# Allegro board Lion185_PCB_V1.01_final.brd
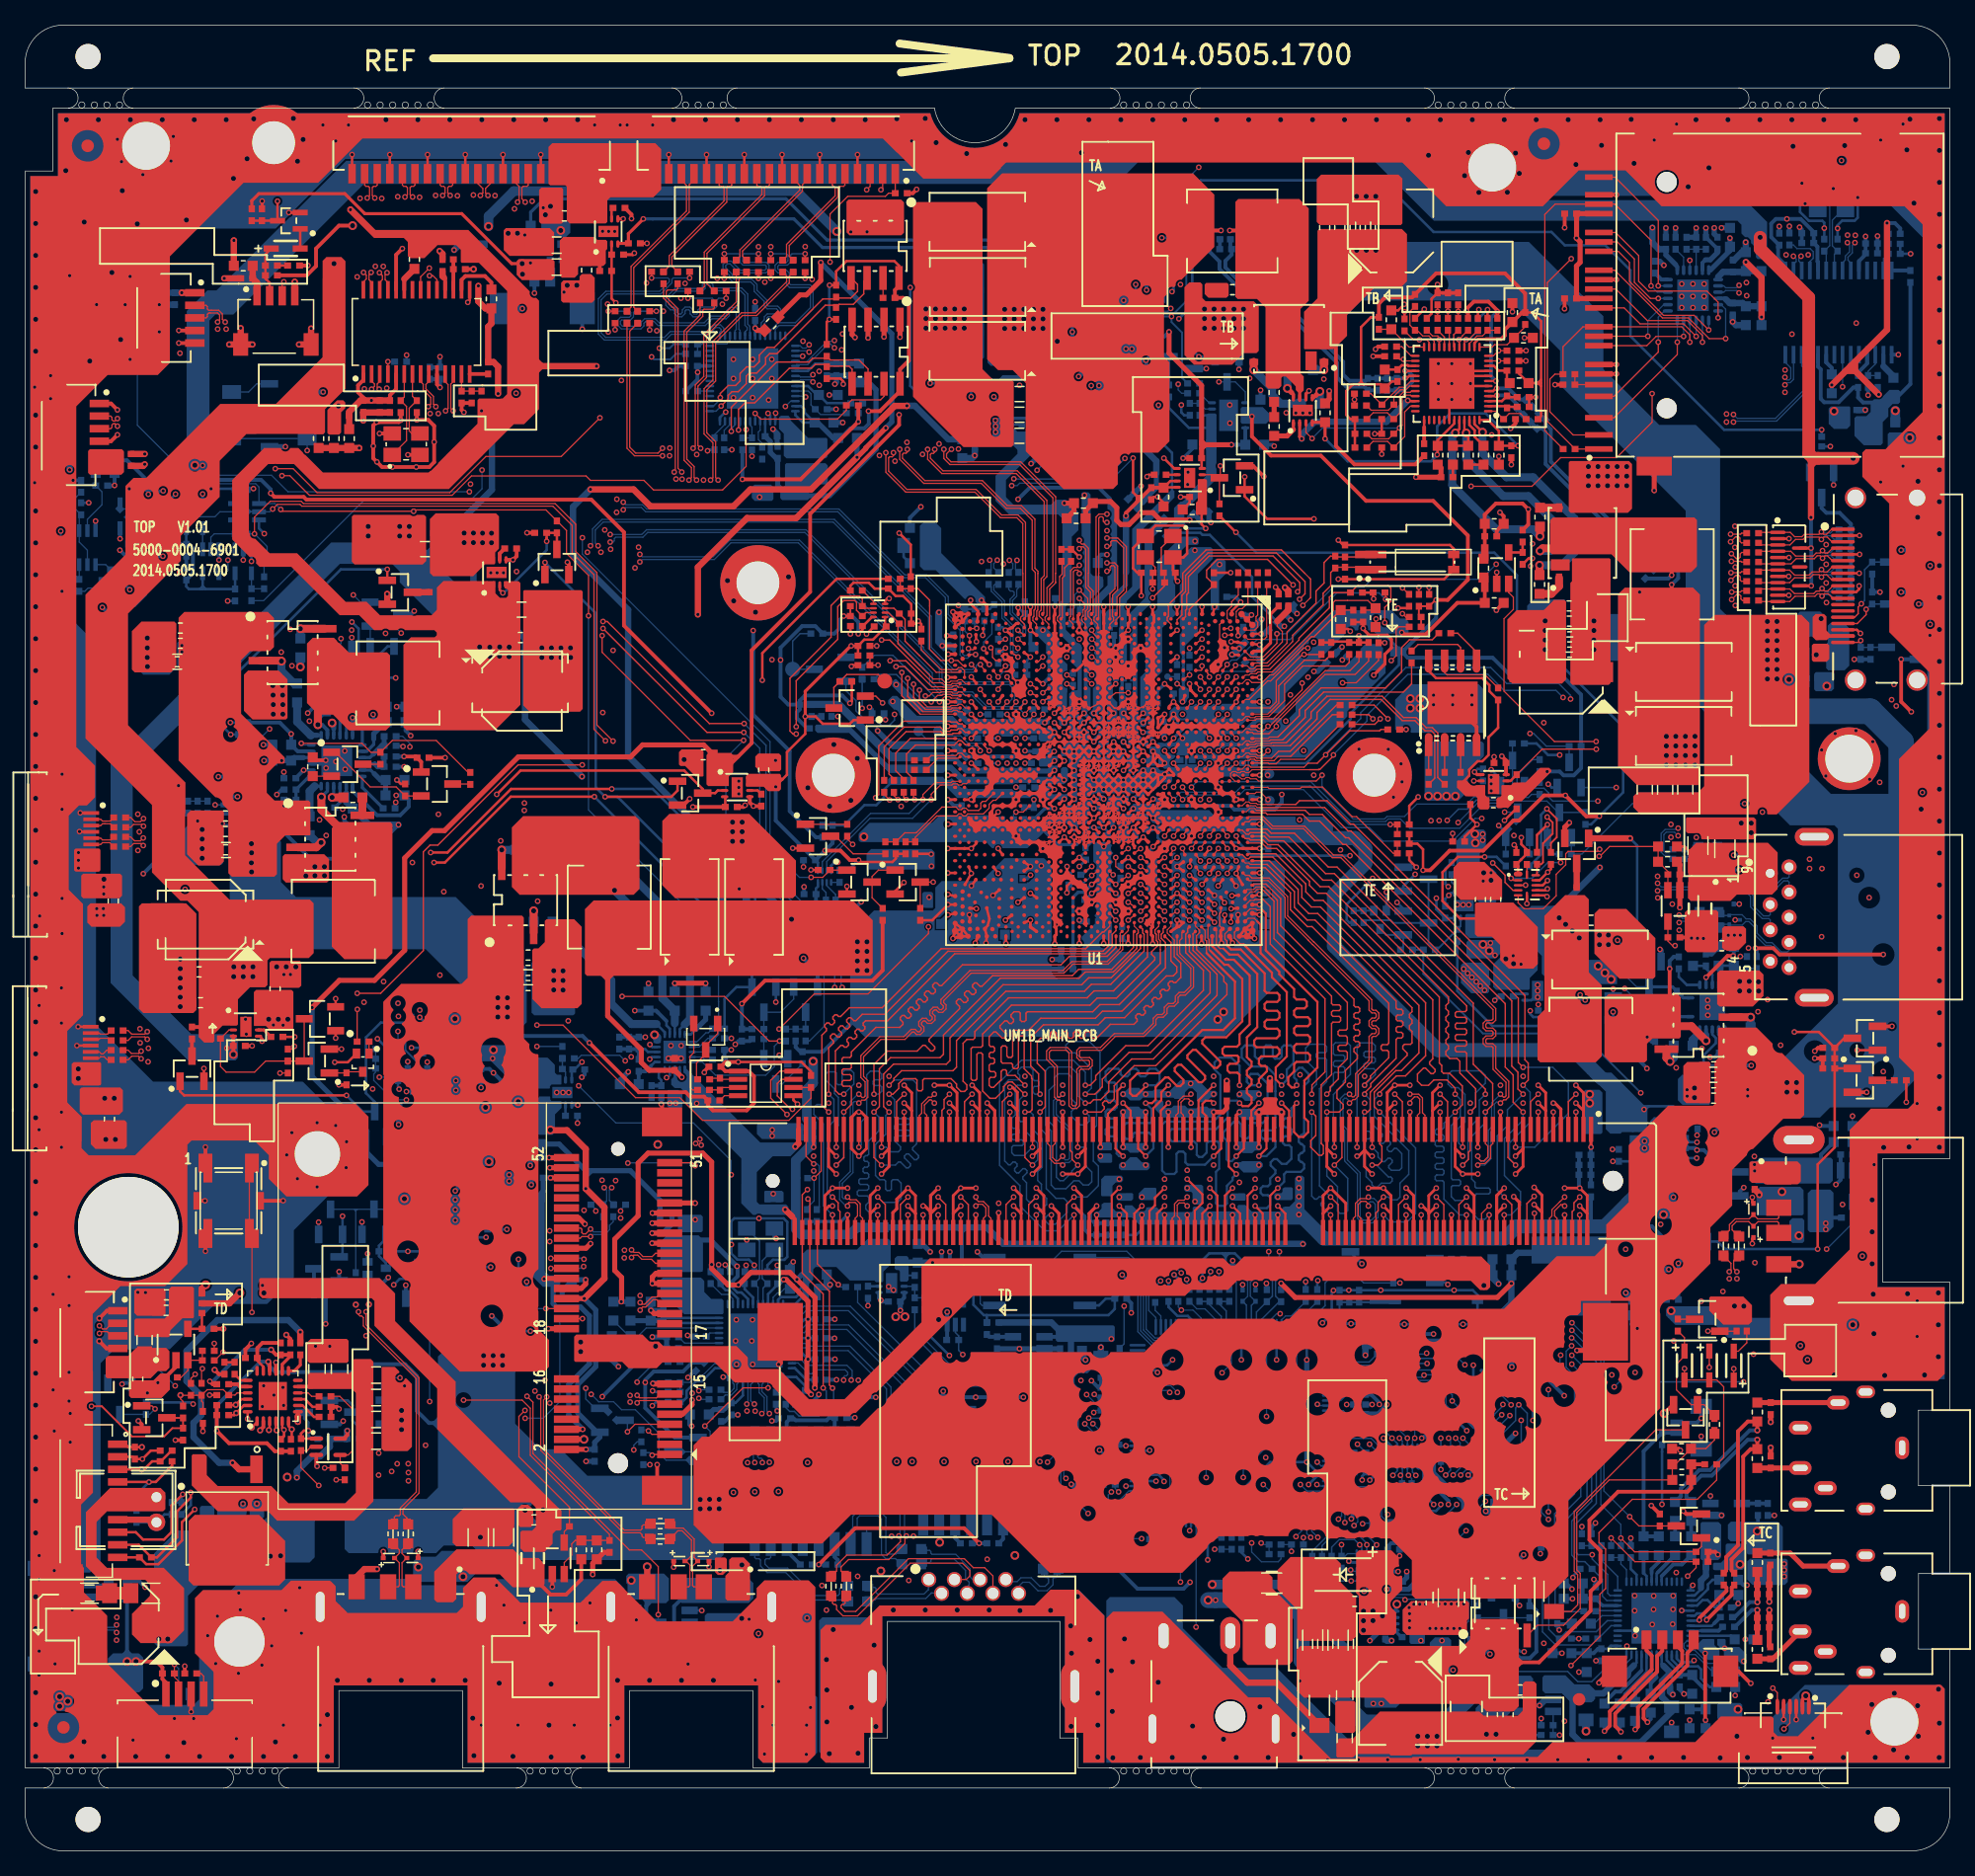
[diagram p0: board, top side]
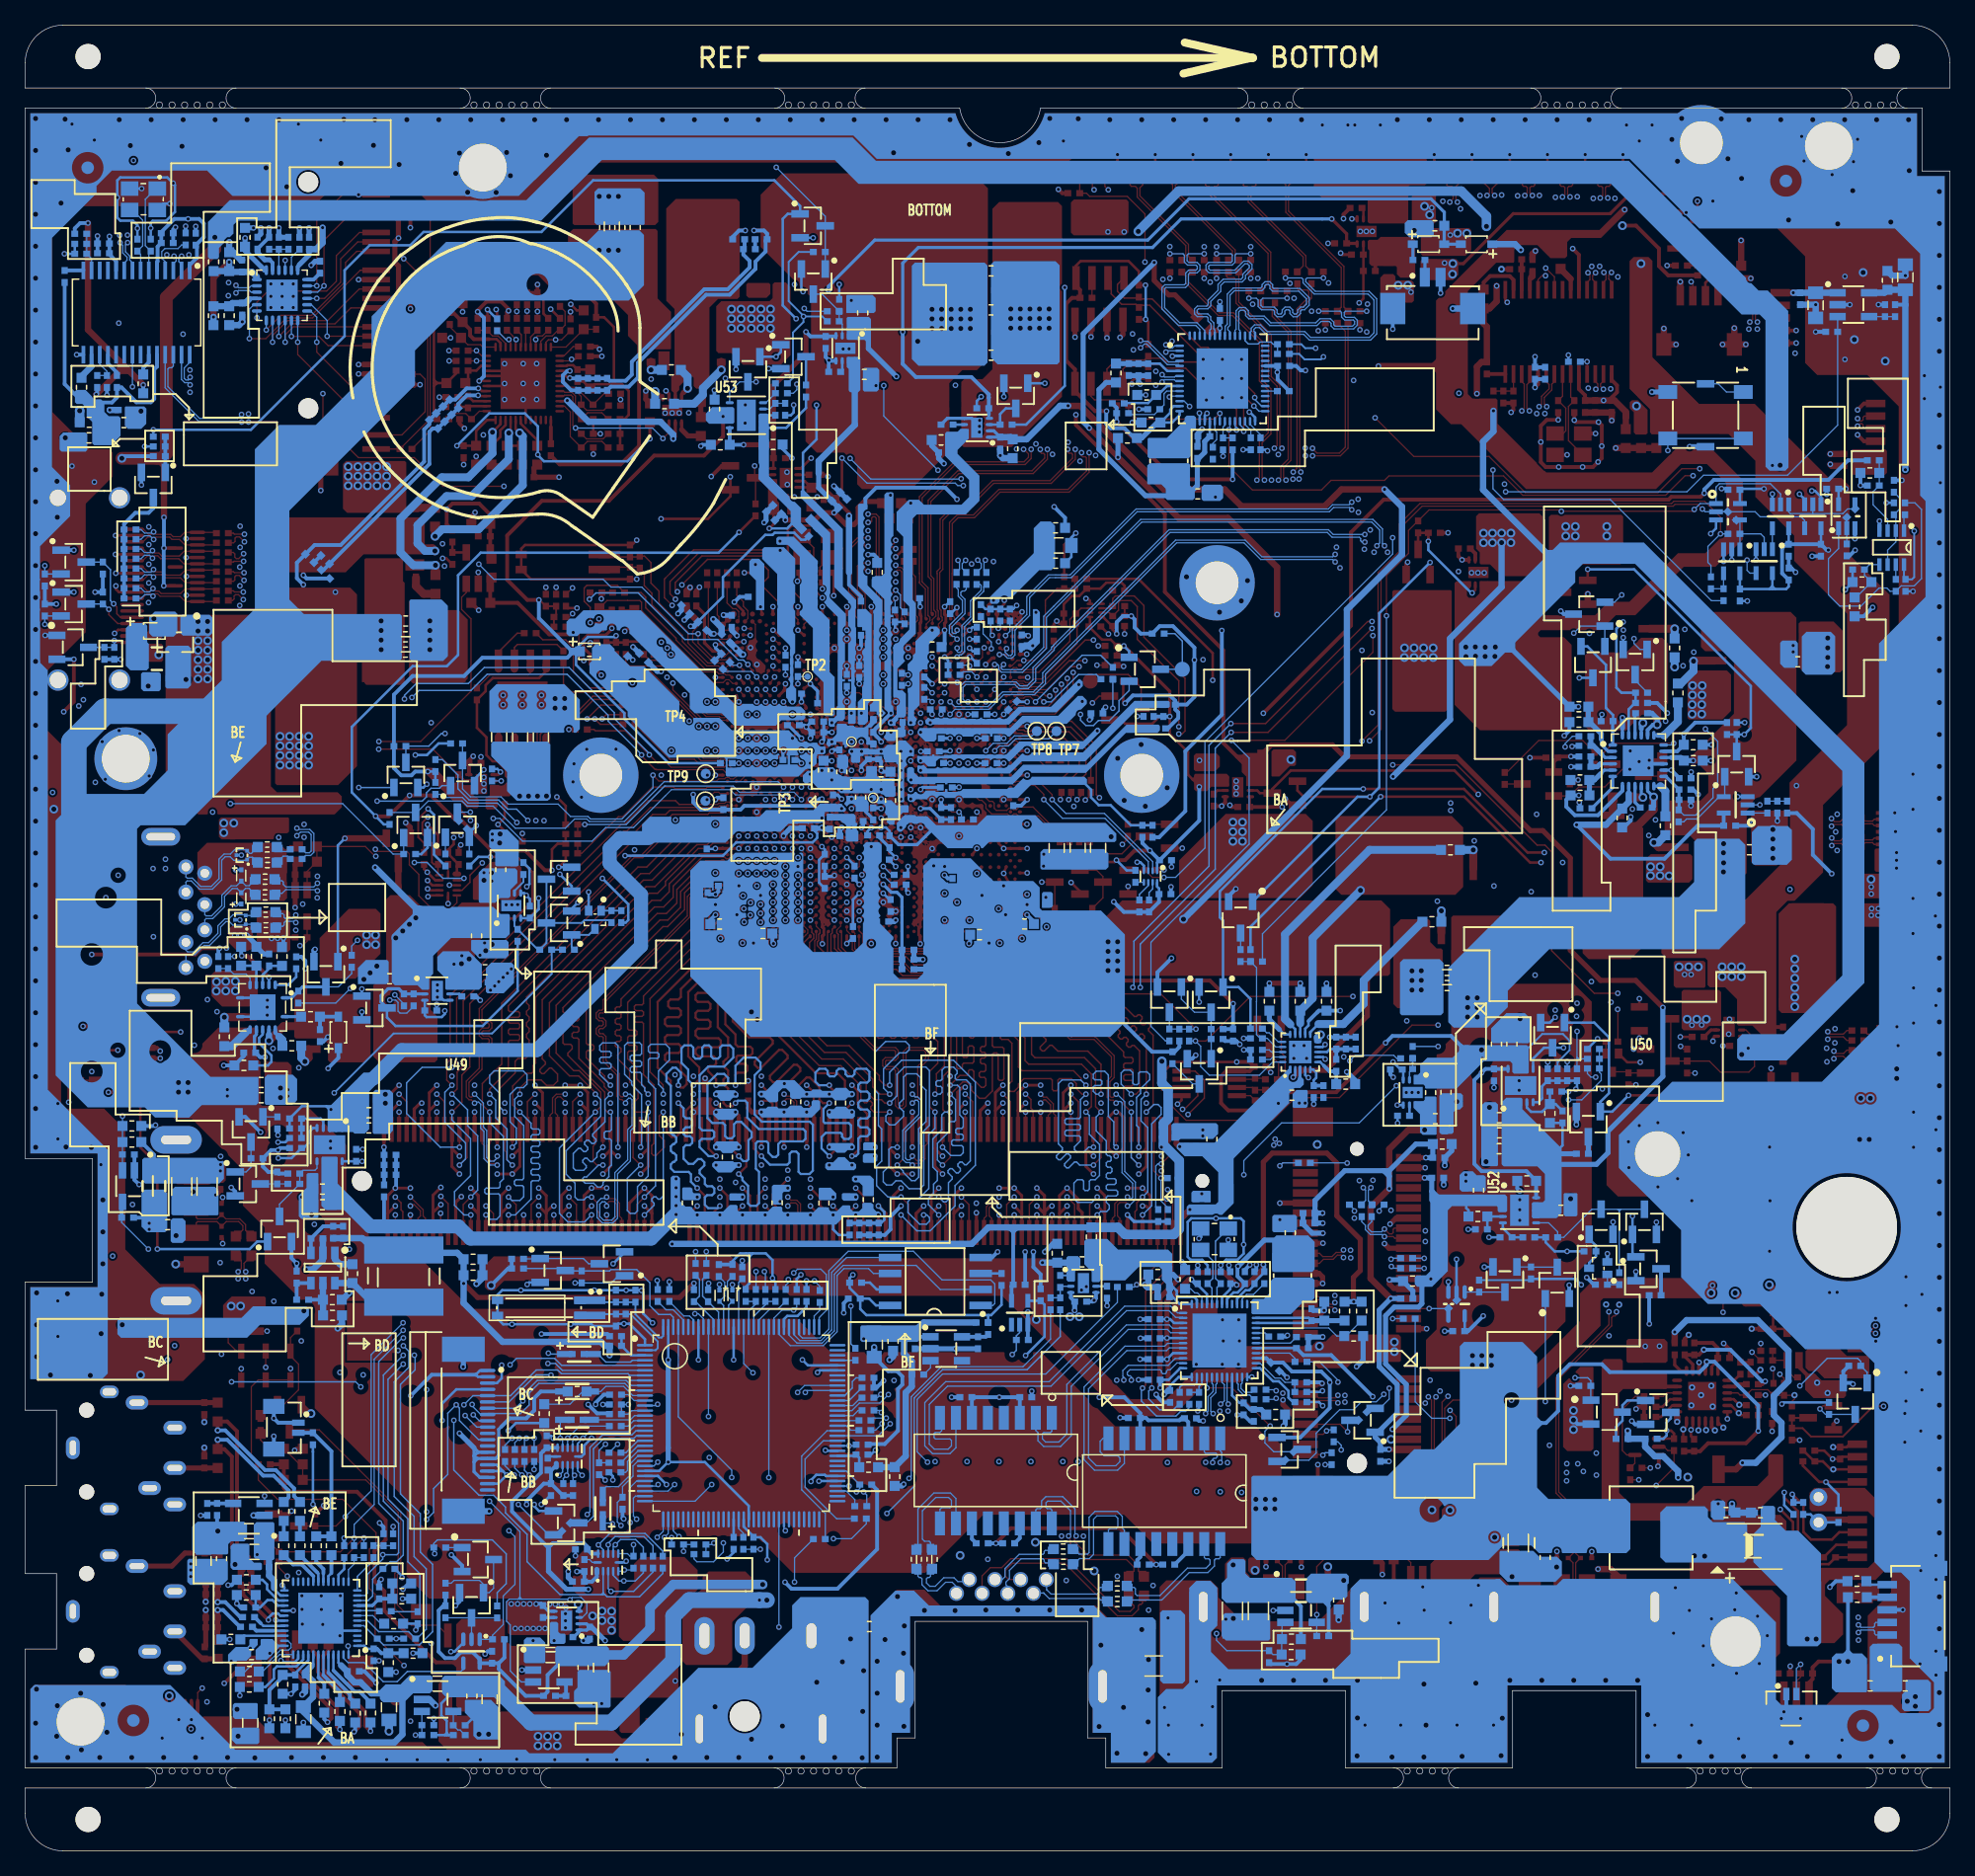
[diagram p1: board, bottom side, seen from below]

Outline 153 x 145.2 mm; copper layers: TOP, LAY2, LAY3, LAY4, LAY5, BOTTOM. Coordinates in mm from the lower left corner of the outline.

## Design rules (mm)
net group 8625_RST#: nets 8625_RST# VDDIO_8625
net group +V3.3A_RTC: nets +V3.3A_RTC VBAT
net group +V5S_HDMI: nets +V5S_HDMI SCL_CONN
net group +V_LED: nets +V_LED N373550150
net group EDP_TXN2: nets EDP_TXN2 EDP_TXN2_CONN
net group EDP_TXN3: nets EDP_TXN3 EDP_TXN3_CONN
net group HDA_BITCLK: nets HDA_BITCLK N370398495
net group HDA_RST#: nets HDA_RST# N370397174
net group HDA_SDATAIN0: nets HDA_SDATAIN0 N371025596
net group HDA_SDATAOUT: nets HDA_SDATAOUT N370398555
net group HDA_SYNC: nets HDA_SYNC N370398430
net group HSON: nets HSON PCIE_RXN0_LAN
net group HSOP: nets HSOP PCIE_RXP0_LAN
net group HUB2_USB_PN1: nets HUB2_USB_PN1 N373557631
net group HUB2_USB_PP1: nets HUB2_USB_PP1 N373557637
net group HUB_USB_PN2: nets HUB_USB_PN2 N373557825
net group HUB_USB_PP2: nets HUB_USB_PP2 N373557823
net group LAN_TX0N: nets LAN_TX0N N373748211
net group LAN_TX0P: nets LAN_TX0P N373748197
net group LAN_TX1N: nets LAN_TX1N N373748171
net group LAN_TX1P: nets LAN_TX1P N373748290
net group LAN_TX2N: nets LAN_TX2N N373748155
net group LAN_TX2P: nets LAN_TX2P N373748367
net group LAN_TX3N: nets LAN_TX3N N373748377
net group LAN_TX3P: nets LAN_TX3P N373748142
net group LAN_VDDEN_SOC: nets LAN_VDDEN_SOC N371123996
net group M_DDR_A_CTRL_IG: nets M_ODT0 M_ODT1
net group M_HDMI_CTL: nets HDMI_CTRLCLK HDMI_CTRLDATA
net group M_HUB2_USB_P2: nets HUB2_USB_PN2 HUB2_USB_PP2
net group M_HUB2_USB_P3: nets HUB2_USB_PN3 HUB2_USB_PP3
net group M_HUB_USB_P3: nets HUB_USB_PN3 HUB_USB_PP3
net group M_HUB_USB_P4: nets HUB_USB_PN4 HUB_USB_PP4
net group M_MDI0: nets MDI0+ MDI0-
net group M_MDI1: nets MDI1+ MDI1-
net group M_MDI2: nets MDI2+ MDI2-
net group M_MDI3: nets MDI3+ MDI3-
net group M_PCIE_RX1_WLAN: nets PCIE_RXN1_WLAN PCIE_RXP1_WLAN
net group M_USB_NFC: nets USB_NFCN USB_NFCP
net group M_USB_P2: nets USB_PN2 USB_PP2
net group M_USB_P3: nets USB_PN3 USB_PP3
net group OUT_CLK+: nets OUT_CLK+ TMDS_CLKP
net group OUT_CLK-: nets OUT_CLK- TMDS_CLKN
net group OUT_D0+: nets OUT_D0+ TMDS_DATAP0
net group OUT_D0-: nets OUT_D0- TMDS_DATAN0
net group OUT_D1+: nets OUT_D1+ TMDS_DATAP1
net group OUT_D1-: nets OUT_D1- TMDS_DATAN1
net group OUT_D2+: nets OUT_D2+ TMDS_DATAP2
net group OUT_D2-: nets OUT_D2- TMDS_DATAN2
net group PCIE_TXN0_LAN: nets N370399343 PCIE_TXN0_LAN
net group PCIE_TXN1_WLAN: nets N370399448 PCIE_TXN1_WLAN
net group PCIE_TXP0_LAN: nets N370399144 PCIE_TXP0_LAN
net group PCIE_TXP1_WLAN: nets N370399202 PCIE_TXP1_WLAN
net group SATA_RXN0: nets N373530908 SATA_RXN0
net group SATA_RXN1: nets N373530772 SATA_RXN1
net group SATA_RXP0: nets N373530977 SATA_RXP0
net group SATA_RXP1: nets N373530802 SATA_RXP1
net group SATA_TXN0: nets N373530916 SATA_TXN0
net group SATA_TXN1: nets N373530783 SATA_TXN1
net group SATA_TXP0: nets N373530914 SATA_TXP0
net group SATA_TXP1: nets N373530781 SATA_TXP1
net group SPI_CLK: nets N371989349 SPI_CLK
net group SPI_CS0#: nets N371989315 SPI_CS0#
net group SPI_SI: nets N371989334 SPI_SI
net group SPI_SO: nets N371989320 SPI_SO
net group USB3_RX0_N: nets N342323571 USB3_RX0_N
net group USB3_RX0_P: nets N342323527 USB3_RX0_P
net group USB_PN0: nets N342323565 USB_PN0
net group USB_PP0: nets N342323609 USB_PP0
net group 40OHM(A_CTL): nets M_CKE0 M_CKE1 M_CS#0 M_CS#1
net group 50OHM: nets H_PROCHOT# SMB_CLK_S2 SMB_DATA_S2
net group 50OHM(A_D0): nets M_A_DQ0 M_A_DQ1 M_A_DQ2 M_A_DQ3 M_A_DQ4 M_A_DQ5 M_A_DQ6 M_A_DQ7
net group 50OHM(A_D1): nets M_A_DQ8 M_A_DQ9 M_A_DQ10 M_A_DQ11 M_A_DQ12 M_A_DQ13 M_A_DQ14 M_A_DQ15
net group 50OHM(A_D2): nets M_A_DQ16 M_A_DQ17 M_A_DQ18 M_A_DQ19 M_A_DQ20 M_A_DQ21 M_A_DQ22 M_A_DQ23
net group 50OHM(A_D3): nets M_A_DQ24 M_A_DQ25 M_A_DQ26 M_A_DQ27 M_A_DQ28 M_A_DQ29 M_A_DQ30 M_A_DQ31
net group 50OHM(A_D4): nets M_A_DQ32 M_A_DQ33 M_A_DQ34 M_A_DQ35 M_A_DQ36 M_A_DQ37 M_A_DQ38 M_A_DQ39
net group 50OHM(A_D5): nets M_A_DQ40 M_A_DQ41 M_A_DQ42 M_A_DQ43 M_A_DQ44 M_A_DQ45 M_A_DQ46 M_A_DQ47
net group 50OHM(A_D6): nets M_A_DQ48 M_A_DQ49 M_A_DQ50 M_A_DQ51 M_A_DQ52 M_A_DQ53 M_A_DQ54 M_A_DQ55
net group 50OHM(A_D7): nets M_A_DQ56 M_A_DQ57 M_A_DQ58 M_A_DQ59 M_A_DQ60 M_A_DQ61 M_A_DQ62 M_A_DQ63
net group 85OHM: nets CLK_PCIE_LAN_N CLK_PCIE_LAN_P CLK_PCIE_WLAN_N CLK_PCIE_WLAN_P
net group AUXN_LVDS: nets AUXN_LVDS EDP_AUXN EDP_AUXN_CONN
net group AUXP_LVDS: nets AUXP_LVDS EDP_AUXP EDP_AUXP_CONN
net group DEFAULT: nets DDR3_DRAM_PWROK DDR3_VCCA_PWROK DDR3L_DRAMRST# EDP_VDDEN
net group EDP_TXN0: nets EDP_TXN0 EDP_TXN0_CONN TXN0_LVDS
net group EDP_TXN1: nets EDP_TXN1 EDP_TXN1_CONN TXN1_LVDS
net group EDP_TXP0: nets EDP_TXP0 EDP_TXP0_CONN TXP0_LVDS
net group EDP_TXP1: nets EDP_TXP1 EDP_TXP1_CONN TXP1_LVDS
net group EDP_TXP2: nets EDP_TXP2 EDP_TXP2_CONN LAO_DATAP2
net group EDP_TXP3: nets EDP_TXP3 EDP_TXP3_CONN LAO_DATAP3
net group GND: nets GND
net group HDMI_CTL_CON: nets SDA_CONN
net group HUB_USB_PN1: nets N373557456
net group HUB_USB_PP1: nets N373557462
net group LPC_CLK_EC: nets LPC_CLK_EC N370732942 N370732965
net group M_DDR_A_CLK: nets M_CLK_DDR0 M_CLK_DDR1 M_CLK_DDR#0 M_CLK_DDR#1
net group M_DDR_A_CMD_IG: nets M_A_A0 M_A_A1 M_A_A2 M_A_A3 M_A_A4 M_A_A5 M_A_A6 M_A_A7 M_A_A8 M_A_A9 M_A_A10 M_A_A11 M_A_A12 M_A_A13 M_A_A14 M_A_A15 M_A_BS0 M_A_BS1 M_A_BS2 M_A_CAS# M_A_RAS# M_A_WE#
net group M_DDR_A_D0: nets M_A_DM0 M_A_DQS0 M_A_DQS#0
net group M_DDR_A_D1: nets M_A_DM1 M_A_DQS1 M_A_DQS#1
net group M_DDR_A_D2: nets M_A_DM2 M_A_DQS2 M_A_DQS#2
net group M_DDR_A_D3: nets M_A_DM3 M_A_DQS3 M_A_DQS#3
net group M_DDR_A_D4: nets M_A_DM4 M_A_DQS4 M_A_DQS#4
net group M_DDR_A_D5: nets M_A_DM5 M_A_DQS5 M_A_DQS#5
net group M_DDR_A_D6: nets M_A_DM6 M_A_DQS6 M_A_DQS#6
net group M_DDR_A_D7: nets M_A_DM7 M_A_DQS7 M_A_DQS#7
net group NET_+V1.05S: nets +V1.05S
net group NET_+V1.8S: nets +V1.8S
net group NET_+V3.3A: nets +V3.3A
net group NET_+V3.3A_KBC: nets +V3.3A_KBC
net group NET_+V3.3S: nets +V3.3S
net group NET_+V5S: nets +V5S
net group NET_AGND: nets AGND
net group NET_BUF_PLT_RST#: nets BUF_PLT_RST#
net group NET_H_RCIN#: nets H_RCIN#
net group NET_KBC_FAN_SPEED: nets KBC_FAN_SPEED
net group NET_PM_SLP_S3#: nets PM_SLP_S3#
net group NET_PM_SLP_S4#: nets PM_SLP_S4#
net group SVID_CLK: nets N370879306 N371989087 SVID_CLK
net group SVID_DATA: nets N370879346 N371989085 SVID_DATA
net group USB3_TX0_N: nets N342323491 N342323907 USB3_TX0_N
net group USB3_TX0_P: nets N342323548 N342323607 USB3_TX0_P
net group USB_BTN: nets USB_BTN
net group USB_BTP: nets USB_BTP
nets with their own width: min track width 0.102; nets CLK_WLAN_OE#

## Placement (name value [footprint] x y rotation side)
C1  100NF  [CC0402N]  82.83 71.66 180 bottom
C3  100NF  [CC0402N]  78.19 101.2 270 bottom
C4  100NF  [CC0402N]  76.59 101.2 270 bottom
C5  100NF  [CC0402N]  77.36 101.2 270 bottom
C6  100NF  [CC0402N]  78.96 101.2 270 bottom
C7  20PF  [CC0402N]  89.2 101.65 0 top
C8  20PF  [CC0402N]  90.96 101.65 180 top
C9  1uF  [CC0603N]  40.94 129.25 180 bottom
C10  1uF  [CC0603N]  107.35 98.08 270 top
C11  12pF  [CC0402N]  104.92 101.62 90 top
C12  1uF  [CC0603N]  104.58 97.93 90 top
C13  100NF  [CC0402N]  100.41 99.48 270 top
C14  12pF  [CC0402N]  104.92 103.38 270 top
C16  100NF  [CC0402N]  114.88 83.7 90 top
C17  1uF  [CC0402N]  118.56 83.34 90 top
C18  1000pF  [CC0402N]  115.89 85.57 270 bottom
C19  100NF  [CC0402N]  117.24 86.52 0 top
C20  0.1u  [CC0402N]  118.54 78.93 90 top
C21  0.1u  [CC0402N]  120.18 78.94 90 top
C22  2.2uF  [CC0603N]  97.79 73.71 180 bottom
C23  2.2uF  [CC0603N]  94.35 72.95 0 bottom
C24  2.2uF  [CC0603N]  77.13 72.87 180 bottom
C25  2.2uF  [CC0603N]  73.56 73.72 0 bottom
C26  0.1u  [CC0402N]  98.75 75.74 270 bottom
C27  0.1u  [CC0402N]  79.28 77.81 90 bottom
C28  0.1u  [CC0402N]  97.42 76.75 180 bottom
C29  0.1u  [CC0402N]  72.34 75.26 0 bottom
C30  1uF  [CC0402N]  84.79 78.83 0 bottom
C31  0.1u  [CC0402N]  84.84 73.91 0 bottom
C32  1uF  [CC0402N]  83.24 88.44 270 bottom
C33  1uF  [CC0402N]  76.4 120.76 0 bottom
C34  1uF  [CC0402N]  76.4 124.11 0 bottom
C35  10uF  [CC0603N]  76.22 125.66 0 bottom
C36  10uF  [CC0603N]  76.22 122.55 0 bottom
C37  10uF  [CC0603N]  76.22 118.95 0 bottom
C38  10uF  [CC0603N]  89.53 85.95 270 bottom
C39  4.7uF  [CC0603N]  84.97 85.82 180 bottom
C40  4.7uF  [CC0603N]  88.08 85.81 90 bottom
C41  2.2uF  [CC0603N]  86.58 83.8 90 bottom
C42  2.2uF  [CC0603N]  84.21 83.53 90 bottom
C43  0.1u  [CC0402N]  86.45 86.83 0 bottom
C44  0.1u  [CC0402N]  84.68 86.82 180 bottom
C45  0.1u  [CC0402N]  84.18 88.11 270 bottom
C46  22uF  [CC0805N]  115.32 88.57 270 bottom
C47  22uF  [CC0805N]  113.65 88.57 270 bottom
C48  22uF  [CC0805N]  112 88.57 270 bottom
C49  1uF  [CC0402N]  97.5 83.29 270 bottom
C50  1uF  [CC0402N]  85.59 82.47 90 bottom
C51  1uF  [CC0402N]  89.43 77.02 90 bottom
C52  1uF  [CC0402N]  89.43 78.79 270 bottom
C53  1uF  [CC0402N]  80.18 82.5 90 bottom
C54  1uF  [CC0402N]  79.4 82.5 90 bottom
C55  1uF  [CC0402N]  73.78 96.23 270 bottom
C56  1uF  [CC0402N]  74.45 83.6 270 bottom
C57  1uF  [CC0402N]  64.1 89.75 90 bottom
C58  1uF  [CC0402N]  84.29 80.26 270 bottom
C59  1uF  [CC0402N]  103.13 94.86 135 bottom
C60  1uF  [CC0402N]  87.76 80.71 180 bottom
C61  1uF  [CC0402N]  83.06 82.4 90 bottom
C62  1uF  [CC0402N]  85.56 80.77 180 bottom
C63  0.1u  [CC0402N]  103.83 95.57 135 bottom
C64  1uF  [CC0402N]  86.51 89.42 90 bottom
C65  1uF  [CC0402N]  89.99 88.96 0 bottom
C66  1uF  [CC0603N]  85.27 101.68 90 bottom
C67  1uF  [CC0402N]  85.57 88.48 270 bottom
C68  1uF  [CC0402N]  89.99 89.81 0 bottom
C69  1uF  [CC0402N]  67.8 90.47 180 bottom
C70  1uF  [CC0402N]  85.57 90.45 270 bottom
C71  1uF  [CC0402N]  87.32 89.47 270 bottom
C72  0.01uF  [CC0402N]  95.05 99.73 180 bottom
C73  1uF  [CC0402N]  105.44 94.68 135 bottom
C74  1uF  [CC0402N]  88.19 89.82 270 bottom
C75  0.01uF  [CC0402N]  80.65 88.48 0 bottom
C76  22uF  [CC0805N]  67.71 79.77 270 bottom
C77  22uF  [CC0805N]  71 79.76 270 bottom
C78  22uF  [CC0805N]  69.33 79.77 270 bottom
C79  1uF  [CC0402N]  79.78 84.57 180 bottom
C80  1uF  [CC0402N]  88.28 88.04 90 bottom
C81  0.47uF  [CC0402N]  98.82 80.16 270 bottom
C83  1uF  [CC0402N]  91.76 92.03 180 bottom
C84  0.1u  [CC0402N]  89.53 91.27 0 bottom
C85  1uF  [CC0402N]  80.47 86.52 180 bottom
C86  0.01uF  [CC0402N]  99.16 97.4 225 bottom
C87  1uF  [CC0402N]  100.49 98.73 45 bottom
C88  1uF  [CC0402N]  96.83 97.79 90 bottom
C89  1uF  [CC0402N]  89.04 81.73 90 bottom
C90  1uF  [CC0402N]  86.86 81.9 0 bottom
C91  1uF  [CC0402N]  90.74 81.33 0 bottom
C92  1uF  [CC0402N]  88 107.16 135 bottom
C93  1uF  [CC0402N]  93.21 106.68 45 bottom
C94  1uF  [CC0402N]  93.75 106.14 45 bottom
C95  1uF  [CC0402N]  88.54 107.7 135 bottom
C96  1uF  [CC0603N]  80.9 95.74 180 bottom
C97  1uF  [CC0402N]  83.24 90.22 270 bottom
C98  1uF  [CC0402N]  82.37 99.62 180 bottom
C99  10uF  [CC0603N]  71.08 102.41 0 bottom
C100  22uF  [CC0805N]  70.84 103.82 180 bottom
C101  0.1u  [CC0402N]  62.04 57.54 0 bottom
C102  0.1u  [CC0402N]  62.04 56.75 0 bottom
C103  0.1u  [CC0402N]  123.99 54.55 0 bottom
C104  0.1u  [CC0402N]  123.99 55.35 0 bottom
C105  10uF  [CC0603N]  58.67 56.6 90 bottom
C106  0.1u  [CC0402N]  85.15 49.45 90 bottom
C107  0.1u  [CC0402N]  85.92 49.45 90 bottom
C108  10uF  [CC0603N]  100.36 51.54 270 bottom
C109  10uF  [CC0603N]  97.35 59.31 270 bottom
C110  10uF  [CC0603N]  85.97 51.79 270 bottom
C111  10uF  [CC0603N]  91.74 59.57 270 bottom
C112  10uF  [CC0603N]  97.18 55.18 90 bottom
C113  10uF  [CC0603N]  88.18 59.48 270 bottom
C114  10uF  [CC0603N]  93.22 51.54 270 bottom
C115  10uF  [CC0603N]  89.51 51.53 270 bottom
C116  1uF  [CC0402N]  59.01 51.39 270 bottom
C117  1uF  [CC0402N]  59.91 56.48 270 bottom
C118  1uF  [CC0402N]  60.69 56.48 270 bottom
C119  1uF  [CC0402N]  59.92 51.39 270 bottom
C120  0.1u  [CC0402N]  98.95 60.11 270 top
C121  0.1u  [CC0402N]  87.71 51.52 270 bottom
C122  0.1u  [CC0402N]  86.08 55.54 90 bottom
C123  0.1u  [CC0402N]  88.12 55.37 90 bottom
C124  0.1u  [CC0402N]  90.07 59.77 270 bottom
C125  0.1u  [CC0402N]  95.52 60.11 270 top
C126  0.1u  [CC0402N]  96.68 51.52 270 bottom
C127  0.1u  [CC0402N]  93.59 59.35 270 bottom
C128  0.1u  [CC0402N]  54.83 62.37 180 top
C129  470pF  [CC0402N]  55.23 60.97 270 top
C130  0.1u  [CC0402N]  18.82 130.12 270 top
C131  0.1u  [CC0402N]  17.61 125.06 0 top
C132  1000pF  [CC0402N]  21.34 126.08 0 top
C133  10uF  [CC0603N]  44.64 125.71 270 top
C134  100NF  [CC0402N]  48.43 127.85 180 top
C135  0.01uF  [CC0402N]  47.21 130.66 180 top
C136  0.1u  [CC0402N]  42.87 131.03 0 top
C137  10uF  [CC0603N]  42.86 130.03 180 top
C138  100NF  [CC0402N]  61.05 126.03 90 top
C140  100NF  [CC0402N]  61.53 125.55 0 top
C141  100NF  [CC0402N]  60.22 126.03 90 top
C142  100NF  [CC0402N]  59.75 125.55 180 top
C143  100NF  [CC0402N]  57.35 126.04 90 top
C144  100NF  [CC0402N]  57.82 125.56 0 top
C150  0.1u  [CC0402N]  58.03 122.2 270 bottom
C151  2.2uF  [CC0603N]  63.84 115.79 180 bottom
C152  1uF  [CC0402N]  63.28 114.65 180 bottom
C153  100NF  [CC0402N]  56.53 126.04 270 top
C154  100NF  [CC0402N]  56.05 125.56 0 top
C155  100NF  [CC0402N]  54.78 123.59 270 top
C156  0.01uF  [CC0402N]  7.31 65.24 180 top
C157  100NF  [CC0402N]  53.65 123.59 270 top
C159  0.01uF  [CC0402N]  7.51 80.64 180 top
C160  1uF  [CC0402N]  65.27 117.81 90 bottom
C161  0.1u  [CC0402N]  64.49 117.8 90 bottom
C162  0.01uF  [CC0402N]  63.73 117.8 90 bottom
C163  0.01uF  [CC0402N]  7.51 79.87 180 top
C164  0.1u  [CC0402N]  52.96 118.1 0 bottom
C165  0.01uF  [CC0402N]  7.31 64.46 180 top
C166  10uF  [CC0603N]  63.5 113.6 0 bottom
C169  10uF  [CC0603N]  59.79 107.92 180 bottom
C171  0.1u  [CC0402N]  59.82 111.22 270 bottom
C172  0.01uF  [CC0402N]  59.3 112.5 180 bottom
C175  0.1u  [CC0402N]  137.32 104.8 0 top
C176  0.1u  [CC0402N]  137.32 104.03 0 top
C177  0.1u  [CC0402N]  137.32 103.26 0 top
C178  0.1u  [CC0402N]  137.32 102.5 0 top
C179  0.1u  [CC0402N]  137.32 101.74 0 top
C180  0.1u  [CC0402N]  137.32 100.97 0 top
C181  0.1u  [CC0402N]  137.32 100.21 0 top
C182  0.1u  [CC0402N]  137.32 99.44 0 top
C183  0.1u  [CC0402N]  142.04 93.25 180 bottom
C184  0.1u  [CC0402N]  142.91 96.13 90 top
C185  0.1u  [CC0402N]  146.7 95.24 90 bottom
C186  20PF  [CC0402N]  59 45.59 90 bottom
C187  20PF  [CC0402N]  57.96 45.59 90 bottom
C188  1uF  [CC0603N]  70.96 47.53 90 bottom
C190  10uF  [CC0603N]  62.97 45.84 0 bottom
C191  0.1u  [CC0402N]  57.2 45.58 90 bottom
C192  0.1u  [CC0402N]  55.28 45.59 90 bottom
C193  0.1u  [CC0402N]  63.25 37.46 0 bottom
C194  0.1u  [CC0402N]  62.5 44.04 0 bottom
C195  0.1u  [CC0402N]  62.5 44.83 0 bottom
C196  0.1u  [CC0402N]  53.64 38.49 225 bottom
C197  4.7uF  [CC0603N]  49.73 42.92 270 bottom
C198  0.1u  [CC0402N]  50.74 42.64 90 bottom
C199  4.7uF  [CC0603N]  52.43 49.15 270 bottom
C200  0.1u  [CC0402N]  53.43 49.02 90 bottom
C201  0.1u  [CC0402N]  56.04 45.59 90 bottom
C202  0.1u  [CC0402N]  61.99 36.14 270 bottom
C203  0.1u  [CC0402N]  63.25 39.1 0 bottom
C204  0.1u  [CC0402N]  63.25 42.28 0 bottom
C205  0.1u  [CC0402N]  51.47 39.98 180 bottom
C206  0.1u  [CC0402N]  59.79 45.58 90 bottom
C207  0.1u  [CC0402N]  63.26 40.77 0 bottom
C208  0.1u  [CC0402N]  54.84 36.67 0 bottom
C209  0.1u  [CC0402N]  54.84 35.91 0 bottom
C210  1uF  [CC0402N]  55.34 34.63 90 bottom
C211  0.1u  [CC0402N]  56.14 35.15 270 bottom
C222  10uF  [CC0805N]  116.08 12.05 90 bottom
C223  10uF  [CC0805N]  138.82 23.05 90 bottom
C224  1uF  [CC0603N]  137.39 23.24 270 bottom
C225  100NF  [CC0402N]  111.84 19.03 270 bottom
C226  1uF  [CC0603N]  117.49 12.31 270 bottom
C227  0.01uF  [CC0402N]  118.5 9.98 0 bottom
C228  0.01uF  [CC0402N]  138.52 27.15 90 bottom
C229  100NF  [CC0402N]  108.12 17.32 90 bottom
C230  4.7uF  [CC0603N]  135.42 20.35 0 bottom
C231  2.2uF  [CC0603N]  136.65 16.82 0 bottom
C232  100NF  [CC0402N]  135.15 19.36 180 bottom
C233  10uF  [CC0603N]  135 15.6 180 bottom
C234  100NF  [CC0402N]  134.37 16.6 180 bottom
C235  10uF  [CC0603N]  135.42 21.56 0 bottom
C236  4.7uF  [CC0603N]  132.44 24.27 270 bottom
C237  4.7uF  [CC0603N]  131.16 24.27 270 bottom
C238  10uF  [CC0805N]  107.22 14.58 90 bottom
C239  100NF  [CC0402N]  134.09 22.57 180 bottom
C240  10uF  [CC0805N]  134.78 23.78 0 bottom
C241  1uF  [CC0603N]  108.65 14.58 270 bottom
C242  0.01uF  [CC0402N]  109.53 12.32 0 bottom
C243  100NF  [CC0402N]  131.52 13.52 90 bottom
C244  10uF  [CC0603N]  132.52 13.24 270 bottom
C245  2.2uF  [CC0603N]  135.18 14.27 0 bottom
C246  10uF  [CC0603N]  135.18 13.03 180 bottom
C247  100NF  [CC0402N]  130.75 13.52 90 bottom
C248  10uF  [CC0805N]  124.08 11.41 270 bottom
C249  2.2uF  [CC0603N]  128.66 24.27 270 bottom
C250  2.2uF  [CC0603N]  129.86 24.27 270 bottom
C251  100NF  [CC0402N]  126.91 14.28 0 bottom
C252  10uF  [CC0805N]  130.88 10.47 270 bottom
C253  10uF  [CC0603N]  123.71 18.07 0 bottom
C254  10uF  [CC0603N]  124.13 14.97 270 bottom
C255  100NF  [CC0402N]  125.3 15.59 90 bottom
C256  100NF  [CC0402N]  124.86 20.52 270 bottom
C257  22pF  [CC0402N]  122.44 16.88 180 bottom
C259  22pF  [CC0402N]  124.08 22.42 0 bottom
C260  22pF  [CC0402N]  121.8 18.54 90 bottom
C261  22pF  [CC0402N]  124.54 16.88 0 bottom
C262  100NF  [CC0402N]  115.88 15.4 270 bottom
C263  10uF  [CC0603N]  40.35 56.21 180 bottom
C264  0.1u  [CC0402N]  40.63 55.13 0 bottom
C265  0.1u  [CC0402N]  45.27 31.45 90 bottom
C266  10uF  [CC0603N]  42.72 45.32 0 bottom
C267  0.1u  [CC0402N]  40.71 53.53 0 bottom
C268  0.1u  [CC0402N]  43.16 43.93 0 bottom
C269  0.1u  [CC0402N]  50.94 50.72 180 bottom
C270  0.1u  [CC0402N]  50.94 49.93 180 bottom
C271  0.1u  [CC0402N]  62.95 16.29 0 bottom
C272  1000pF  [CC1206N]  63.28 14.71 180 bottom
C273  0.01uF  [CC0402N]  7.52 82.18 180 top
C274  0.01uF  [CC0402N]  7.52 81.41 180 top
C275  10uF  [CC0603N]  11.21 42.99 180 top
C281  10uF  [CC0603N]  84.01 40.52 90 bottom
C282  10uF  [CC0603N]  83.88 29.77 90 bottom
C283  0.1u  [CC0402N]  86.48 31.51 180 bottom
C284  0.1u  [CC0402N]  109.02 21.41 0 bottom
C285  0.1u  [CC0402N]  108.78 23.97 0 bottom
C286  0.1u  [CC0402N]  111.2 28.73 270 bottom
C287  0.1u  [CC0402N]  111.54 32.54 90 bottom
C288  1uF  [CC0402N]  106.07 34.73 180 bottom
C289  10pF  [CC0402N]  106.04 44.11 90 bottom
C290  0.1u  [CC0402N]  106.07 36.28 0 bottom
C291  10pF  [CC0402N]  106.04 42.21 270 bottom
C292  100NF  [CC0402N]  73.98 45.02 0 bottom
C293  0.1u  [CC0402N]  87.09 43.92 0 bottom
C294  47pF  [CC0402N]  72.28 44.22 90 bottom
C296  4.7uF  [CC1206N]  5.12 20.49 180 top
C297  4.7uF  [CC1206N]  10 20.49 180 top
C298  10uF  [CC1210N]  34.3 24.49 270 bottom
C299  10uF  [CC0603N]  7.01 75.54 270 top
C300  10uF  [CC0603N]  6.7 58.2 270 top
C301  10uF  [CC0603N]  8.95 37.52 270 top
C302  100NF  [CC0402N]  67.97 97.37 180 top
C303  0.1u  [CC0402N]  9.94 37.61 90 top
C304  1uF  [CC0603N]  11.23 44.21 180 top
C305  0.01uF  [CC0402N]  14.54 41.52 180 top
C309  10uF  [CC0603N]  134.88 71.99 0 top
C310  10uF  [CC1206N]  132.98 79.95 270 top
C311  10uF  [CC1206N]  135.12 79.7 270 top
C312  1000pF  [CC0402N]  136.51 80.24 90 top
C313  0.1u  [CC0402N]  131.06 77.65 0 top
C314  100NF  [CC0402N]  131.46 78.89 180 bottom
C315  100NF  [CC0402N]  131.46 79.65 180 bottom
C316  10uF  [CC1206N]  140.55 52.83 90 bottom
C317  1000pF  [CC0402N]  137.49 53.08 270 top
C318  0.1u  [CC0402N]  144.79 55.38 180 bottom
C319  10uF  [CC1206N]  138.54 52.83 90 bottom
C320  10uF  [CC0603N]  141.67 49.8 180 bottom
C321  0.1u  [CC0402N]  10.25 103.44 270 bottom
C322  10uF  [CC1206N]  36.01 24.93 270 top
C323  1000pF  [CC0402N]  34.6 24.11 90 top
C324  0.1u  [CC0402N]  9.32 108.33 0 bottom
C325  0.1u  [CC0402N]  46.45 24.21 270 top
C326  0.1u  [CC0402N]  17.16 108.25 0 bottom
C327  10uF  [CC1206N]  57.02 19.07 90 bottom
C328  1000pF  [CC0402N]  55.79 22.94 180 top
C329  0.1u  [CC0402N]  12.81 103.44 270 bottom
C330  0.1u  [CC0402N]  54.12 15.45 270 bottom
C331  0.1u  [CC0402N]  16.69 99.88 270 bottom
C332  0.1u  [CC0402N]  12.81 101.55 90 bottom
C333  10uF  [CC1206N]  54.97 19.08 90 bottom
C334  10uF  [CC0603N]  48.59 19.94 270 bottom
C335  10uF  [CC1206N]  38.05 24.93 270 top
C336  10uF  [CC0603N]  40.45 26.32 180 top
C337  1000pF  [CC0402N]  85.9 16.05 0 bottom
C338  0.01uF  [CC0402N]  62.94 17.88 180 bottom
C360  4.7uF  [CC0603N]  12.09 94.57 180 bottom
C361  4.7uF  [CC0603N]  12.09 94.57 180 top
C362  10uF  [CC0805N]  12.09 94.57 180 top
C363  0.1uF  [CC0603N]  12.34 97.25 0 top
C364  0.1uF  [CC0603N]  15.92 81.07 0 top
C365  10uF  [CC0805N]  15.97 79.59 180 top
C366  4.7uF  [CC0603N]  15.94 79.62 180 top
C367  4.7uF  [CC0603N]  15.94 79.61 180 bottom
C368  10uF  [CC0603N]  26.05 82.15 90 bottom
C369  0.1u  [CC0402N]  24.51 90.48 180 bottom
C370  0.1u  [CC0402N]  24.14 82.98 0 bottom
C371  0.1u  [CC0402N]  39.51 97.51 0 top
C372  2.2uF  [CC0603N]  39.37 96.49 0 top
C373  0.1u  [CC0402N]  13.75 68.88 180 top
C374  2.2uF  [CC0603N]  13.83 69.91 180 top
C375  4.7uF  [CC0603N]  20.4 87.97 180 bottom
C376  0.1uF  [CC0603N]  20.39 86.71 0 bottom
C377  0.1u  [CC0402N]  35.39 85.29 270 top
C378  0.1u  [CC0402N]  28.24 86.89 270 top
C379  1uF  [CC0603N]  22.86 86.22 90 top
C380  0.1u  [CC0402N]  31.63 86.94 0 top
C381  0.1u  [CC0402N]  30.21 84.38 90 top
C382  10uF  [CC0805N]  39.97 69.48 0 bottom
C383  0.1uF  [CC0603N]  39.98 71.24 0 top
C384  10uF  [CC0805N]  39.98 69.48 0 top
C385  0.1u  [CC0402N]  51.64 62.55 270 top
C386  0.1uF  [CC0603N]  51.64 67.57 90 bottom
C387  10uF  [CC0603N]  52.31 60.1 180 bottom
C388  1uF  [CC0603N]  49.55 67.57 270 bottom
C389  100pF  [CC0402N]  138.76 35.17 270 top
C390  100pF  [CC0402N]  138.76 30.93 90 top
C391  0.1u  [CC0402N]  60.89 75.7 90 top
C392  0.1uF  [CC0603N]  48.03 60.98 0 bottom
C393  0.22uF  [CC0402N]  50.57 60.39 270 bottom
C394  0.01uF  [CC0402N]  48.77 64.24 270 bottom
C395  100NF  [CC0402N]  86.58 116.41 0 bottom
C396  100NF  [CC0402N]  79.91 111.21 180 bottom
C397  1uF  [CC0402N]  87.42 122.14 270 bottom
C398  1000pF  [CC0402N]  88.65 117.62 180 bottom
C399  1uF  [CC0402N]  75.49 111.96 90 bottom
C400  1000pF  [CC0402N]  79.72 113.43 180 bottom
C401  100NF  [CC0402N]  89.36 119.97 90 bottom
C402  100NF  [CC0402N]  76.87 114.73 180 bottom
C403  100NF  [CC0402N]  116.68 69.07 0 bottom
C404  0.1u  [CC0402N]  129.56 64.84 90 bottom
C405  0.1uF  [CC0603N]  134.22 59.87 0 top
C406  10uF  [CC0805N]  134.23 61.72 180 top
C407  4.7uF  [CC0603N]  134.23 61.09 180 top
C408  1uF  [CC0402N]  123.94 70.38 180 bottom
C409  1000pF  [CC0402N]  117.81 67.96 0 bottom
C410  100NF  [CC0402N]  120.76 66.83 0 bottom
C411  1uF  [CC0402N]  135.15 63.47 0 bottom
C412  0.1uF  [CC0603N]  124.48 74.01 0 top
C413  1uF  [CC0402N]  133.61 70.86 90 bottom
C414  100NF  [CC0402N]  114.2 78.11 270 bottom
C415  1uF  [CC0402N]  115.01 72.6 90 bottom
C416  1000pF  [CC0402N]  113.39 78.12 270 bottom
C417  100NF  [CC0402N]  112.88 74.66 270 bottom
C418  10uF  [CC0603N]  129.37 52.63 0 bottom
C419  0.1u  [CC0402N]  129.61 53.64 0 bottom
C420  10uF  [CC0603N]  125.68 58.71 180 bottom
C421  0.1u  [CC0402N]  125.53 59.7 180 bottom
C422  100NF  [CC0402N]  59.71 85.69 270 top
C423  10uF  [CC0603N]  36.04 64.16 90 bottom
C424  0.1u  [CC0402N]  33.79 64.05 90 bottom
C425  10uF  [CC0603N]  35.82 58.31 0 bottom
C426  0.1u  [CC0402N]  35.76 54.81 0 bottom
C427  1uF  [CC0402N]  54.04 86.18 0 top
C428  1000pF  [CC0402N]  58.52 83.57 90 top
C429  100NF  [CC0402N]  56.13 83.02 180 top
C430  10uF  [CC0603N]  30.91 50.95 180 bottom
C431  1uF  [CC0603N]  33.64 53.28 0 bottom
C432  10uF  [CC0603N]  37.47 52.54 90 bottom
C433  0.1u  [CC0402N]  38.48 52.27 90 bottom
C434  100NF  [CC0402N]  89.52 107.94 90 top
C435  10uF  [CC0603N]  98.2 114.67 90 bottom
C436  1uF  [CC0603N]  97.74 111.83 0 bottom
C437  10uF  [CC0603N]  35.83 55.84 0 bottom
C438  10uF  [CC0603N]  93.54 111.85 180 bottom
C439  1uF  [CC0402N]  93.04 107.67 0 top
C440  1000pF  [CC0402N]  90.22 109.44 0 top
C441  100NF  [CC0402N]  93.04 110.76 0 top
C442  0.22uF  [CC0402N]  29.01 87.88 180 bottom
C443  4.7uF  [CC0603N]  134.23 62.36 180 top
C444  4.7uF  [CC0603N]  134.23 59.9 180 bottom
C445  10uF  [CC0603N]  124.03 69.36 0 bottom
C446  10uF  [CC0603N]  116.44 70.08 180 bottom
C447  1000pF  [CC0402N]  20.01 64.74 180 top
C448  0.22uF  [CC0402N]  119.08 115.61 0 top
C449  100pF  [CC0402N]  118.26 117.72 0 top
C450  4.7uF  [CC0603N]  122.77 96.56 180 bottom
C451  4.7uF  [CC0603N]  122.77 95.34 180 bottom
C452  4.7uF  [CC0603N]  122.77 95.34 180 top
C453  4.7uF  [CC0603N]  122.77 96.55 180 top
C454  10uF  [CC0805N]  122.75 95.96 180 bottom
C455  10uF  [CC0805N]  122.76 95.94 180 top
C456  1uF  [CC0603N]  122.74 99.01 180 top
C457  4.7uF  [CC0603N]  122.75 97.8 180 top
C458  4.7uF  [CC0603N]  122.75 97.81 180 bottom
C459  4.7uF  [CC0603N]  134.24 61.11 180 bottom
C460  0.01uF  [CC0402N]  85.9 16.84 0 bottom
C461  1000pF  [CC0402N]  62.94 17.08 0 bottom
C462  3900pF  [CC0402N]  119.45 114.54 225 bottom
C463  270pF  [CC0402N]  119.99 114 45 bottom
C464  0.022uF  [CC0402N]  120.54 113.45 45 bottom
C465  1uF  [CC0402N]  116.25 121.41 270 top
C466  0.33UF  [CC0603N]  118.23 122.34 270 top
C467  2.2uF  [CC0603N]  117.15 111 90 top
C468  0.1u  [CC0603N]  114.71 111 270 top
C469  4.7uF  [CC0603N]  112.29 111 270 top
C470  22uF  [CC0805N]  130.37 84.4 270 top
C471  22uF  [CC0805N]  131.97 84.4 270 top
C472  22uF  [CC0805N]  128.75 84.4 270 top
C473  1000pF  [CC0402N]  113.02 109.25 0 top
C474  100pF  [CC0402N]  109.1 117.33 90 top
C475  0.22uF  [CC0402N]  106.15 115.89 180 top
C476  0.022uF  [CC0402N]  106.74 116.64 270 bottom
C477  3900pF  [CC0402N]  108.26 116.64 90 bottom
C478  270pF  [CC0402N]  107.5 116.64 270 bottom
C479  1uF  [CC0603N]  103.33 114.37 270 top
C480  0.1u  [CC0603N]  99.28 115.99 270 top
C481  22uF  [CC0805N]  79.04 114.22 180 top
C482  22uF  [CC0805N]  79.04 112.54 180 top
C483  22uF  [CC0805N]  79.05 115.86 180 top
C484  1000pF  [CC0402N]  93.72 124.16 0 top
C485  4.7uF  [CC0603N]  106.93 129.11 90 bottom
C486  4.7uF  [CC0603N]  105.72 129.11 90 bottom
C487  4.7uF  [CC0603N]  106.93 129.11 90 top
C488  4.7uF  [CC0603N]  105.72 129.11 90 top
C489  10uF  [CC0805N]  106.36 129.18 90 top
C490  10uF  [CC0805N]  106.36 129.18 90 bottom
C491  1uF  [CC0603N]  103.31 129.09 90 top
C492  4.7uF  [CC0603N]  104.51 129.1 90 top
C493  4.7uF  [CC0603N]  104.51 129.1 90 bottom
C494  0.1u  [CC0402N]  78.22 36.08 180 bottom
C495  0.1u  [CC0402N]  73.46 36.08 0 bottom
C496  0.1u  [CC0402N]  64.83 34.43 180 bottom
C497  10uF  [CC0603N]  13.95 67.45 180 top
C498  0.01uF  [CC0402N]  20.87 68.65 270 top
C499  10uF  [CC0603N]  19.87 68.56 90 top
C500  100NF  [CC0402N]  17.02 64.02 180 top
C501  10uF  [CC0805N]  39.47 98.71 180 top
C502  0.01uF  [CC0402N]  32 104.79 0 top
C503  10uF  [CC0805N]  31.78 103.53 0 top
C504  100NF  [CC0402N]  39.52 99.91 180 top
C505  0.1u  [CC0402N]  39.04 41.33 0 bottom
C506  0.1u  [CC0402N]  80.81 87.44 180 bottom
C507  1uF  [CC0402N]  82.27 40.41 90 bottom
C508  100pF  [CC0402N]  138.73 15.75 90 top
C509  100pF  [CC0402N]  138.73 23.21 270 top
C510  100NF  [CC0402N]  69.09 43.68 0 bottom
C511  1000pF  [CC0402N]  67 44.43 90 bottom
C512  100NF  [CC0402N]  40.63 57.24 0 bottom
C513  100NF  [CC0402N]  44 62.14 180 bottom
C514  1000pF  [CC0402N]  43.43 58.46 180 bottom
C515  1uF  [CC0603N]  40.06 60.33 270 bottom
C516  1uF  [CC0603N]  40.91 58.23 180 bottom
C517  100NF  [CC0402N]  125.3 23.8 270 bottom
C518  1uF  [CC0402N]  81.52 93.84 270 bottom
C519  100NF  [CC0402N]  66.08 97.41 180 top
C520  100NF  [CC0402N]  51.87 125.11 270 top
C521  1uF  [CC0402N]  77.26 40.41 90 bottom
C522  100NF  [CC0402N]  50.75 125.11 270 top
C523  100NF  [CC0402N]  48.69 121.97 270 top
C524  100NF  [CC0402N]  49.17 121.5 180 top
C525  100NF  [CC0402N]  47.84 121.97 270 top
C526  100NF  [CC0402N]  47.37 121.5 0 top
C527  0.1u  [CC0402N]  60.37 34.4 0 bottom
C529  10uF  [CC0603N]  35.82 57.1 0 bottom
C535  1000pF  [CC0402N]  38.59 103.58 180 top
C536  10uF  [CC0603N]  129.37 51.39 0 bottom
C537  10uF  [CC0603N]  125.68 57.49 180 bottom
C538  10uF  [CC0603N]  34.81 64.16 90 bottom
C539  100NF  [CC0402N]  143.37 62.23 180 top
C540  0.1u  [CC0402N]  17.5 81.53 180 bottom
C542  4.7uF  [CC0603N]  39.98 68.82 0 top
C543  4.7uF  [CC0603N]  39.98 70.02 0 top
C544  4.7uF  [CC0603N]  39.97 68.82 0 bottom
C545  4.7uF  [CC0603N]  39.98 70.02 0 bottom
C546  4.7uF  [CC0603N]  12.34 96.04 180 top
C547  4.7uF  [CC0603N]  15.93 82.31 180 top
C548  10uF  [CC0603N]  116.78 99.25 180 top
C549  0.01uF  [CC0402N]  119.04 102.79 90 top
C550  10uF  [CC0603N]  53.9 87.18 180 top
C551  10uF  [CC0603N]  58.71 85.96 90 top
C552  10uF  [CC0603N]  90.5 107.67 270 top
C553  10uF  [CC0603N]  92.77 106.68 180 top
C554  10uF  [CC0603N]  117.12 72.77 270 bottom
C555  10uF  [CC0603N]  115.2 78.03 90 bottom
C556  10uF  [CC0603N]  74.5 111.51 270 bottom
C557  10uF  [CC0603N]  80.19 112.21 0 bottom
C558  10uF  [CC0603N]  86.42 122.31 90 bottom
C559  10uF  [CC0603N]  86.3 117.42 180 bottom
C560  10uF  [CC0603N]  116.78 105.54 180 top
C561  1uF  [CC0402N]  116.51 104.55 0 top
C562  1uF  [CC0402N]  126.69 55.31 90 bottom
C563  22pF  [CC0402N]  131.51 58.24 180 bottom
C564  22pF  [CC0402N]  30.79 58.37 90 bottom
C565  1uF  [CC0402N]  36.24 61.71 270 bottom
C566  100NF  [CC0402N]  62.35 78.78 180 bottom
C567  100NF  [CC0402N]  62.39 76.09 180 bottom
C568  4.7uF  [CC0603N]  128.58 43.83 180 bottom
C569  0.1u  [CC0603N]  126.98 45.91 90 bottom
C570  22pF  [CC0402N]  128.52 49.2 90 bottom
C571  10uF  [CC0603N]  117.4 45.78 0 bottom
C572  10uF  [CC0603N]  117.4 47.05 0 bottom
C573  1uF  [CC0402N]  28.19 114.87 90 top
C574  0.1u  [CC0402N]  29 114.87 90 top
C575  1uF  [CC0402N]  32.17 117.52 270 bottom
C576  0.1u  [CC0402N]  32.98 117.52 270 bottom
C577  0.1u  [CC0402N]  26.88 114.88 90 top
C578  1uF  [CC0402N]  34.7 115.62 90 top
C579  20PF  [CC0402N]  29.85 114.86 90 top
C580  20PF  [CC0402N]  31.13 114.86 90 top
C581  10uF  [CC0603N]  24.55 112.32 270 top
C582  0.1u  [CC0402N]  25.27 114.12 0 top
C583  100pF  [CC0402N]  138.17 21.18 0 top
C584  100pF  [CC0402N]  138.17 17.77 0 top
C585  0.1uF  [CC0603N]  131.69 30.74 0 top
C586  0.1uF  [CC0603N]  118.83 12.79 180 top
C587  0.1uF  [CC0603N]  116.64 10.83 90 top
C596  1uF  [CC0402N]  115.48 121.37 270 bottom
C597  1uF  [CC0402N]  91.93 89.53 0 bottom
C598  10uF  [CC1210N]  113.13 20.15 270 top
C599  0.1uF  [CC0603N]  110.97 19.71 90 top
C600  0.1uF  [CC0603N]  131.67 31.98 0 top
C601  10UF  [CC1206N]  113.13 20.14 270 top
C602  0.1uF  [CC0603N]  117.88 10.83 90 top
C603  10UF  [CC1206N]  34.3 24.49 270 bottom
C604  4.7uF  [CC1210N]  114.51 11.47 270 top
C605  0.1uF  [CC0603N]  105.69 19.84 180 top
C606  1uF  [CC0402N]  148.58 127.02 180 bottom
C607  0.1uF  [CC0603N]  32.17 23.34 90 bottom
C608  10uF  [CC0603N]  147.91 113.61 180 bottom
C609  0.1u  [CC0402N]  145.13 114.59 180 bottom
C610  0.1u  [CC0402N]  139.44 128.18 270 bottom
C611  0.1u  [CC0402N]  141.71 127.87 0 bottom
C612  1uF  [CC0402N]  141.71 128.65 0 bottom
C613  0.1u  [CC0402N]  146.78 127.06 180 bottom
C614  1uF  [CC0402N]  146.78 127.84 180 bottom
C615  20PF  [CC0402N]  144.08 127.71 270 bottom
C616  20PF  [CC0402N]  143.02 127.71 270 bottom
C617  0.1u  [CC0402N]  69.64 131.83 180 top
C618  10uF  [CC0805N]  3.54 125.15 270 bottom
C619  1uF  [CC0603N]  4.96 124.9 90 bottom
C620  0.01uF  [CC0402N]  5.15 122.49 270 bottom
C621  0.1u  [CC0402N]  11.9 123.44 90 bottom
C622  10uF  [CC0805N]  10.67 122.92 90 bottom
C700  4.7uF  [CC0603N]  136.78 126.39 90 bottom
C701  0.1u  [CC0402N]  135.75 126.05 90 bottom
C702  0.1u  [CC0402N]  135.74 122.62 90 bottom
C703  2.2uF  [CC0603N]  136.78 122.09 270 bottom
C704  4.7uF  [CC0603N]  135.52 128.33 90 bottom
C705  0.1u  [CC0402N]  134.53 127.86 90 bottom
C706  1uF  [CC0402N]  129.57 125.95 270 bottom
C707  0.1u  [CC0402N]  132.83 127.85 90 bottom
C708  0.1u  [CC0402N]  122.85 123.46 180 top
C709  0.1u  [CC0402N]  122.85 130.21 180 top
C710  0.1u  [CC0402N]  130.43 127.85 270 bottom
C726  0.1u  [CC0402N]  3.52 100.65 90 bottom
C727  470nF  [CC0402N]  15.84 38.39 90 top
C764  0.1u  [CC0402N]  6.08 108.58 180 bottom
C765  0.1u  [CC0402N]  7.26 101.9 180 bottom
C766  100NF  [CC0402N]  28.33 63.77 0 bottom
C767  100NF  [CC0402N]  56.98 64.88 270 bottom
C845  2.2uF  [CC0805N]  104.9 8.96 90 top
C942  0.1u  [CC0402N]  42.92 131.92 0 top
C992  2.2uF  [CC0402N]  21.08 39.92 270 top
CN2  1.25T-2-2PWB-T  [SMD-CN-125P-2WBN]  41.11 122.66 180 bottom
CN3  0705A1BA52E/0705A1BE52E  [SMD-DDR-60X1020P-204N-R]  92.83 53.28 0 top
CN4  CN4+2-S  [SMD-CN-100P-4BN]  19.93 119.81 0 top
CN5  XF2U-0615-3A  [SMD-FPC-50P-6N-OR]  140.54 8.6 0 top
CN6  WB2012DR-02T2  [TH-CN-200P-2N-H]  10.44 27.13 270 top
CN8  HM21XX-191B-41XX-004  [SMD-HDMI-CN-50P-19AN]  145.5 100.36 90 top
CN9  RJB-2X08X-XX-XX-017  [TH-RJ45-102X110P-8AN]  75.4 9.17 0 top
CN11  C1.0T-1-6AB  [SMD-CN-100P-6L]  1.1 18.67 90 bottom
CN12  43-42109-052XXRHF  [SMD-PCIE-80X820P-52BN-L]  47.13 43.33 90 top
CN13  XF2U-0415-3A  [SMD-FPC-100P-4N-JS]  12.69 10.57 0 top
CN14  F2T20U-XXT3-E  [SMD-CN-50P-20N-H]  118.57 33.45 270 bottom
CN15  BXNC041-91-50  [SMD-USB-200X250P-4BN]  139.4 50.15 90 top
CN16  CN20+2-S  [SMD-CN-100P-20L]  35.49 137.26 180 top
CN17  C1.0T-1-6AB  [SMD-CN-100P-6L]  3.49 40.46 270 top
CN18  CN20+2-S  [SMD-CN-100P-20L]  59.67 137.26 180 top
CN19  1008R-02P-SM  [SMD-CN-80P-2N]  12.6 12.47 180 bottom
CN20  BAR 1.25T-2-4PWB-T  [SMD-CN-125P-4N-JS]  130.76 14.28 0 top
CN21  1008R-02P-SM  [SMD-CN-80P-2N]  131.28 33.65 270 bottom
CN22  C1.0T-1-6AB  [SMD-CN-100P-6L]  2.02 112.61 270 top
CN24  AFC04-S14ECA-00  [SMD-FPC-50P-14N]  3.18 79.04 270 top
CN26  AFC04-S14ECA-00  [SMD-FPC-50P-14N]  3.14 62.04 270 top
CN27  BXNC041-91-50  [SMD-USB-200X250P-4BN]  52.95 21 0 top
CN28  BXNC041-91-50  [SMD-USB-200X250P-4BN]  29.85 21 0 top
CN30  1030-20001-110  [SMD-CN-CARD-75P-22N]  130.5 123.73 90 top
CN34  F2T06U-A1T3-E  [SMD-CN-50P-6N-H]  140.79 9.14 0 top
CP1  330uF  [CCP7343N]  57.94 75.06 90 top
CP4  220UF  [CAE630W570HN]  39.51 92.25 0 top
CP5  150uF  [CCP7343N]  39.35 92.87 0 top
CP6  150uF  [CCP7343N]  14.34 74.07 180 top
CP7  220UF  [CAE630W570HN]  14.34 74.07 180 top
CP9  330uF  [CCP7343N]  52.82 75.07 90 top
CP11  330uF  [CCP7343N]  125.19 70.89 0 top
CP12  330uF  [CCP7343N]  131.84 88.67 0 top
CP13  330uF  [CCP7343N]  131.85 93.77 0 top
CP14  330uF  [CCP7343N]  75.69 119.29 180 top
CP18  330uF  [CCP7343N]  75.71 124.38 180 top
CP19  100uF  [CAE660W800HN]  109.34 11.73 270 top
CP20  330uF  [CCP7343N]  75.69 129.57 180 top
CP25  100uF  [CAE660W800HN]  122.11 93.75 180 top
CP26  100uF  [CAE660W800HN]  108.63 128.83 90 top
CP50  10UF  [CAE630W570HN]  7.43 18.02 180 top
D1  BAT54WS-7-F  [SOD1713N]  37.62 127.78 0 bottom
D2  BAT54WS-7-F  [SOD1713N]  41.45 127.78 180 bottom
D3  1SS355TE17  [SOD2514N]  20.71 127.44 180 top
D5  BAT54WS-7-F  [SOD1713N]  142.74 97.02 180 bottom
D6  D_2PN  [SOT95P280-3N]  149.22 95.72 180 bottom
D7  1SS355TE17  [SOD2514N]  109.12 36.53 0 bottom
D9  1SS355TE17  [SOD2514N]  109.13 34.28 0 bottom
D10  1SS355TE17  [SOD2514N]  107.08 27.22 270 bottom
D11  1SS355TE17  [SOD2514N]  108.97 39.51 0 bottom
D12  AOZ8231  [SOD0806N]  135.82 77.57 90 bottom
D13  AOZ8231  [SOD0806N]  135.82 75.75 270 bottom
D14  SK34  [SOD5227N]  104.76 21.97 0 top
D15  1SS355TE17  [SOD2514N]  135.82 38.59 270 top
D24  D_2PN  [SOT95P280-3N]  32.74 84.85 0 top
D25  D_2PN  [SOT95P280-3N]  25.61 86.42 0 top
D26  BAT54WS-7-F  [SOD1713N]  128.1 65.09 90 bottom
D27  AOZ8231  [SOD0806N]  96.78 44.16 90 bottom
D28  AOZ8231  [SOD0806N]  97.81 44.15 90 bottom
D31  BAT54WS-7-F  [SOD1713N]  108.15 95.39 180 bottom
D33  1SS355TE17  [SOD2514N]  131.91 38.59 90 top
D34  1SS355TE17  [SOD2514N]  133.88 38.6 90 top
D38  B2100  [SOD5336N]  15.48 24.21 180 bottom
D41  DFLS1100-7  [SOD2818N]  15.48 24.21 180 bottom
D44  AOZ8231  [SOD0806N]  137.39 51.05 90 top
D45  AOZ8231  [SOD0806N]  137.39 49.22 270 top
D46  AOZ8231  [SOD0806N]  28.92 23.29 180 top
D47  AOZ8231  [SOD0806N]  30.79 23.29 0 top
D48  AOZ8231  [SOD0806N]  52 23.05 180 top
D49  AOZ8231  [SOD0806N]  53.91 23.05 0 top
F1  3216FF-5A  [F1206N]  99.1 21.3 180 top
F2  1206L110//NANOSMDC110F  [F1206N]  142.53 94.82 180 bottom
F3  1206L110//NANOSMDC110F  [F1206N]  133.15 74.94 90 top
F4  1206L110//NANOSMDC110F  [F1206N]  142.76 52.87 90 bottom
F5  1206L110//NANOSMDC110F  [F1206N]  40.34 23.28 270 top
F6  1206L110//NANOSMDC110F  [F1206N]  51.58 20.69 0 bottom
FB1  180  [FB0603N]  17.34 126.06 180 top
FB2  180  [FB0603N]  66.29 117.53 270 bottom
FB3  180  [FB0603N]  65.37 112.36 0 bottom
FB4  220  [FB0603N]  138.02 126.39 90 bottom
FB5  120  [FB0805N]  135.21 25.42 0 bottom
FB6  120  [FB0805N]  120.22 13.3 180 bottom
FB7  120  [FB0805N]  111.25 15.57 180 bottom
FB8  180ohm  [FB0603N]  133.59 10.5 270 bottom
FB9  180ohm  [FB0603N]  132.31 10.5 270 bottom
FB10  180ohm  [FB0603N]  122.17 15.72 0 bottom
FB11  120  [FB0805N]  135.11 10.18 90 bottom
FB12  120  [FB0805N]  9.5 40.63 90 top
FB13  180  [FB0603N]  85.95 30.51 0 bottom
FB14  220  [FB0603N]  37.06 123.42 90 top
FB15  220  [FB0603N]  25.76 112.32 270 top
FB16  180  [FB0603N]  59.31 121.46 225 top
FB17  220  [FB0603N]  148.52 116.4 90 bottom
FB18  220  [FB0603N]  145.16 113.59 0 bottom
FB20  220  [FB0603N]  138.03 122.09 270 bottom
FB23  120R  [FB0805N]  104.99 16.46 90 top
FB24  120R  [FB0805N]  101.74 16.46 90 top
FB25  120R  [FB0805N]  103.35 16.46 90 top
FB32  47  [FB0603N]  85.89 17.84 180 bottom
FB34  120  [FB1206N]  102.35 16.76 270 top
FB35  120  [FB1206N]  104.37 16.76 270 top
FB36  120  [FB1206N]  99.1 21.3 0 top
FIL1  330mA  [FIL_175P200X120-4L]  81.53 23.19 180 bottom
FIL2  330mA  [FIL_175P200X120-4L]  64.68 21.05 0 top
FIL3  330mA  [FIL_175P200X120-4L]  70.48 23.4 270 bottom
FIL4  330mA  [FIL_175P200X120-4L]  66.19 20.45 270 bottom
FIL5  330mA  [FIL_175P200X120-4L]  133.93 76.65 270 bottom
FIL6  330mA  [FIL_175P200X120-4L]  133.86 74.04 270 bottom
FIL7  330mA  [FIL_175P200X120-4L]  133.75 79.22 270 bottom
FIL12  330mA  [FIL_175P200X120-4L]  135.6 48.1 180 top
FIL13  330mA  [FIL_175P200X120-4L]  29.85 25.2 180 top
FIL14  330mA  [FIL_175P200X120-4L]  50.49 25.42 90 top
J2  1UF4XXXXXRCXX  [TH-USB-200X150P-9GN]  140.37 74.25 90 top
J3  5pin  [SMD-CN-100P-5L]  9.61 121.92 270 top
J4  PJ-353D  [TH-EARPHONE-6BN]  145.61 19.05 270 top
J5  C1.0T-1-10AWB  [SMD-CN-100P-10L]  7.36 27.84 270 top
J7  PJ-353D  [TH-EARPHONE-6BN]  145.61 32.05 270 top
J13  DJ440G-11XX0-0030  [TH-CN-DCIN-530X740P-5N]  95.8 10.7 0 top
L3  2.2uH  [LC3030DL]  62.07 110.55 90 bottom
L4  2.2uH  [LC3030DL]  52.25 45.76 90 bottom
L6  2.2uH  [LC6666N]  29.64 92.89 180 top
L7  2.2uH  [LC6666N]  24.5 73.93 180 top
L8  1.0uH  [LC6666N]  46.43 75.06 270 top
L9  1.5uH  [LC6666N]  124.47 64.55 180 top
L14  0.36uH  [LC7266N]  130.89 101.52 0 top
L15  0.36uH  [LC7266N]  95.95 128.87 270 top
L16  10UH  [LC4340N]  122.9 45.71 0 bottom
L17  4.7uH  [LC5757N]  122.9 45.71 90 bottom
L31  10uH  [LC6666N]  23.75 25.68 180 bottom
MARK1  MARK  [MARK-D100D250]  4.97 135.6 0 top
MARK2  MARK  [MARK-D100D250]  120.73 135.77 0 top
MARK3  MARK  [MARK-D100D250]  123.53 12.05 0 top
MARK4  MARK  [MARK-D100D250]  3.04 9.82 0 top
MARK5  MARK  [MARK-D100D250]  6.91 9.96 180 bottom
MARK6  MARK  [MARK-D100D250]  144.4 10.37 180 bottom
MARK7  MARK  [MARK-D100D250]  148.03 133.86 180 bottom
MARK8  MARK  [MARK-D100D250]  13.03 132.81 180 bottom
MH1  H  [MTG400H600]  17.03 16.65 0 top
MH2  H  [MTG340H600]  64.24 85.55 0 top
MH3  H  [MTG340H600]  107.24 85.55 0 top
MH4  H  [MTG340H600]  58.25 100.85 0 top
MH5  H  [MTG340H600]  19.75 135.85 0 top
MH6  H  [MTG380H500]  145 86.86 0 top
MH7  H  [MTG380H500]  148.6 10.27 0 top
MH8  H  [MTG380H500]  9.61 135.6 0 top
MH9  H  [MTG380H500]  116.62 133.87 0 top
MH10  H  [MTG340R580]  23.23 55.43 0 top
NOREF  -  [unnamed]  8.2 49.6 0 top
NOREF#2  -  [unnamed]  5 2.5 0 top
NOREF#3  -  [unnamed]  148 142.7 0 top
NOREF#4  -  [unnamed]  5 142.7 0 top
NOREF#5  -  [unnamed]  148 2.5 0 top
Q1  2N7002LT1  [SOT95P240-3N]  118.23 85.72 90 bottom
Q2  2N7002LT1  [SOT95P240-3N]  121.96 81.59 90 bottom
Q3  2N7002LT1  [SOT95P240-3N]  122.74 85.57 90 bottom
Q4  MMBT3904  [SOT95P230-3N]  54.1 64.75 270 top
Q5  DTC144EUA  [SOT65P210-3N]  20.96 129.65 180 top
Q7  BSS138  [SOT95P280-3N]  7.52 35.96 270 bottom
Q8  2N7002LT1  [SOT95P240-3N]  142.81 108.63 270 bottom
Q9  2N7002LT1  [SOT95P240-3N]  149.14 102.5 180 bottom
Q10  2N7002LT1  [SOT95P240-3N]  149.14 99.16 180 bottom
Q13  2N7002LT1  [SOT95P240-3N]  117.52 19.53 270 bottom
Q14  BSS138  [SOT95P280-3N]  117.01 23.17 180 bottom
Q16  BSS138  [SOT95P280-3N]  27.28 34.89 180 bottom
Q17  2N7002LT1  [SOT95P240-3N]  23.18 34.87 180 bottom
Q25  WNM4002-3/TR  [SOT50P160-3N]  107.71 74.05 270 bottom
Q34  APM4910K  [SOIC127P600-8N]  24.25 80.45 0 top
Q35  APM4910K  [SOIC127P600-8N]  21.25 95.29 0 top
Q36  BSS138  [SOT95P280-3N]  56.38 74.24 270 bottom
Q37  APM4910K  [SOIC127P600-8N]  39.79 75.61 90 top
Q38  2N7002LT1  [SOT95P240-3N]  58.73 67.7 270 bottom
Q39  2N7002LT1  [SOT95P240-3N]  62.04 67.7 270 bottom
Q40  APM4910K  [SOIC127P600-8N]  133.02 65.67 180 top
Q41  SM7302ESKP  [KPAK127P605-9N]  123.84 104.03 90 top
Q42  APM2301CAa8  [SOT95P280-3N]  28.37 94.54 270 bottom
Q43  2N7002LT1  [SOT95P240-3N]  25.01 94.55 270 bottom
Q44  WNM4002-3/TR  [SOT50P160-3N]  26.84 62.68 270 top
Q45  2N7002LT1  [SOT95P240-3N]  23.18 62.81 180 top
Q46  2N7002LT1  [SOT95P240-3N]  66.32 77.05 0 top
Q47  2N7002LT1  [SOT95P240-3N]  70.15 77.05 0 top
Q48  2N7002LT1  [SOT95P240-3N]  146.26 64.63 180 top
Q49  2N7002LT1  [SOT95P240-3N]  129.09 69.72 270 bottom
Q50  2N7002LT1  [SOT95P240-3N]  31.58 64.87 270 bottom
Q51  2N7002LT1  [SOT95P240-3N]  23.96 46.29 180 bottom
Q52  2N7002LT1  [SOT95P240-3N]  95.54 117.83 270 bottom
Q53  2N7002LT1  [SOT95P240-3N]  146.24 61.28 0 top
Q54  2N7002LT1  [SOT95P240-3N]  42.27 102.5 90 top
Q55  2N7002LT1  [SOT95P240-3N]  29.79 100.09 0 top
Q56  2N7002LT1  [SOT95P240-3N]  13.26 62.21 90 top
Q57  2N7002LT1  [SOT95P240-3N]  123.34 79.53 270 top
Q58  2N7002LT1  [SOT95P240-3N]  28.74 57.79 270 bottom
Q59  2N7002LT1  [SOT95P240-3N]  91.93 118.83 180 bottom
Q61  2N7002LT1  [SOT95P240-3N]  59.67 62 270 bottom
Q62  2N7002LT1  [SOT95P240-3N]  118.64 81.61 90 bottom
Q63  2N7002LT1  [SOT95P240-3N]  111.06 46.16 180 bottom
Q64  2N7002LT1  [SOT95P240-3N]  52.48 31.93 180 bottom
Q65  AO4419  [SOIC127P600-8N]  117.49 19.68 90 top
Q66  2N7002LT1  [SOT95P240-3N]  46.68 34.24 0 bottom
Q67  2N7002LT1  [SOT95P240-3N]  35.37 45.44 270 bottom
Q68  BSS138  [SOT95P280-3N]  31.21 45.17 90 bottom
Q69  2N7002LT1  [SOT95P240-3N]  110 26.08 180 bottom
Q70  WNM4002-3/TR  [SOT50P160-3N]  27.95 46.34 0 bottom
Q71  2N7002LT1  [SOT95P240-3N]  27.72 50.03 90 bottom
Q72  WNM2020-3  [SOT95P240-3BN]  135.05 57.37 270 bottom
Q73  2N7002LT1  [SOT95P240-3N]  135.3 53.04 180 bottom
Q74  2N7002LT1  [SOT95P240-3N]  132.78 49.46 90 bottom
Q75  2N7002LT1  [SOT95P240-3N]  74.25 115.72 270 bottom
Q76  2N7002LT1  [SOT95P240-3N]  90.35 124.81 270 bottom
Q77  2N7002LT1  [SOT95P240-3N]  90.4 129.24 180 bottom
Q78  2N7002LT1  [SOT95P240-3N]  131.99 34.48 270 top
Q79  2N7002LT1  [SOT95P240-3N]  110.56 73.8 0 bottom
Q80  2N7002LT1  [SOT95P240-3N]  110.56 77.28 0 bottom
Q81  2N7002LT1  [SOT95P240-3N]  125.24 67.04 180 bottom
Q82  2N7002LT1  [SOT95P240-3N]  52.86 84.12 0 top
Q83  2N7002LT1  [SOT95P240-3N]  95.94 109.2 180 top
Q84  BSS138  [SOT95P280-3N]  23.43 66.17 180 top
Q85  2N7002LT1  [SOT95P240-3N]  16.95 86.43 90 bottom
Q86  2N7002LT1  [SOT95P240-3N]  24.28 50.02 90 bottom
Q87  SM7302ESKP  [KPAK127P605-9N]  100.46 120.32 180 top
Q88  2N7002LT1  [SOT95P240-3N]  106.35 46.69 0 bottom
Q89  2N7002LT1  [SOT95P240-3N]  133.71 42.28 180 top
Q90  2N7002LT1  [SOT95P240-3N]  10.27 34.44 0 top
Q95  APW1110NU  [SOT229P990-3N]  16.1 27 180 top
Q97  2N7002LT1  [SOT95P240-3N]  132.25 25.84 180 top
Q98  APM2301CAa8  [SOT95P280-3N]  28.67 98.36 0 bottom
Q100  2N7002LT1  [SOT95P240-3N]  63.02 80.69 0 top
Q102  BSS138  [SOT95P280-3N]  65.53 90.89 180 top
Q103  BSS138  [SOT95P280-3N]  63.99 93.97 180 bottom
R1  100k  [RC0402N]  83.44 77.63 0 bottom
R2  100k  [RC0402N]  83.44 76.84 0 bottom
R3  29.4  [RC0402N]  84.21 75.18 270 bottom
R4  23.2  [RC0402N]  87.07 77.84 90 bottom
R5  162  [RC0402N]  87.2 73.03 270 bottom
R6  4.7K  [RC0402N]  82.82 70.12 180 bottom
R7  10k  [RC0402N]  71.15 74.48 90 top
R8  0  [RC0402N]  17.31 106.16 225 bottom
R9  4.7K  [RC0402N]  82.83 70.89 0 bottom
R10  1M  [RC0402N]  63.51 78.01 180 top
R11  10k  [RC0402N]  124.03 82.11 270 bottom
R12  10k  [RC0402N]  118.71 88.07 0 bottom
R13  2.2K  [RC0402N]  109.55 80.86 180 top
R14  10k  [RC0402N]  108.79 89.18 0 top
R15  100k  [RC0402N]  122.44 79.27 0 bottom
R16  10k  [RC0402N]  109.55 81.63 180 top
R17  10k  [RC0402N]  66.07 100.24 180 top
R18  1K  [RC0603N]  7.39 21.45 180 bottom
R19  402  [RC0402N]  83.3 93.17 90 bottom
R20  470  [RC0603N]  7.35 20.17 180 bottom
R22  0  [RC0402N]  82.37 103.03 270 top
R23  0  [RC0402N]  83.85 98.21 270 bottom
R24  0  [RC0402N]  83.14 103.03 270 top
R25  0  [RC0402N]  83.09 98.06 270 bottom
R26  357  [RC0402N]  79.47 98.87 90 bottom
R31  10k  [RC0402N]  109.55 80.1 0 top
R32  10k  [RC0402N]  109.55 79.33 180 top
R33  0  [RC0402N]  79.16 94.29 180 bottom
R34  100k  [RC0402N]  68.16 74.48 270 top
R35  0  [RC0402N]  79.16 93.53 180 bottom
R36  10k  [RC0402N]  66.68 95.83 180 top
R37  402  [RC0402N]  80.57 90.78 0 bottom
R38  0  [RC0402N]  77.34 94.92 270 bottom
R39  10k  [RC0402N]  77.02 98.64 90 bottom
R40  0  [RC0402N]  77.35 96.84 90 bottom
R41  10k  [RC0402N]  75.48 98.29 90 bottom
R42  10k  [RC0402N]  74.72 98.29 90 bottom
R43  10k  [RC0402N]  76.25 98.29 90 bottom
R44  402  [RC0402N]  81.52 92.06 270 bottom
R45  49.9  [RC0402N]  77.02 90.39 180 bottom
R46  49.9  [RC0402N]  76.2 88.48 180 bottom
R47  33  [RC0402N]  70.62 84.66 270 top
R48  33  [RC0402N]  69.06 84.66 270 top
R49  33  [RC0402N]  69.84 84.66 270 top
R50  33  [RC0402N]  68.29 84.66 270 top
R51  10k  [RC0402N]  69.99 79.77 270 top
R52  10k  [RC0402N]  69.21 79.77 270 top
R53  10k  [RC0402N]  70.75 79.77 90 top
R54  10k  [RC0402N]  68.38 79.77 90 top
R55  49.9  [RC0402N]  76.21 86.5 0 bottom
R56  4.7K  [RC0402N]  69.09 101.16 180 top
R57  100k  [RC0402N]  69.09 100.39 180 top
R58  5.6k  [RC0402N]  70.4 100.86 270 top
R59  1M  [RC0402N]  90.1 100.88 180 top
R60  47.5  [RC0402N]  86.69 93.8 270 bottom
R61  4.02K  [RC0402N]  87.68 93.09 270 bottom
R62  10k  [RC0402N]  110.49 97.35 0 top
R63  10k  [RC0402N]  120.39 84.5 90 bottom
R64  2.2K  [RC0402N]  107.58 95.61 90 top
R65  20K  [RC0402N]  106.36 98.2 270 top
R66  1K  [RC0402N]  42.21 126.52 180 bottom
R67  100k  [RC0402N]  105.83 100.07 0 top
R68  20K  [RC0402N]  105.58 98.2 90 top
R69  10M  [RC0402N]  104.14 102.5 270 top
R70  22  [RC0402N]  111.57 85.3 90 top
R71  3.3K  [RC0402N]  114.11 85.3 270 top
R72  3.3K  [RC0402N]  117.09 92.01 270 top
R73  22  [RC0402N]  112.84 85.3 270 top
R74  22  [RC0402N]  112.85 96.84 0 top
R75  22  [RC0402N]  110.21 94.95 270 top
R76  10k  [RC0402N]  97.26 86.5 0 bottom
R77  0  [RC0603N]  116.71 83.36 180 top
R78  49.9  [RC0402N]  92.29 86.76 0 bottom
R79  1k  [RC0402N]  118.56 85.11 270 top
R80  10k  [RC0402N]  103.04 95.63 270 top
R81  100k  [RC0402N]  113.85 46.32 180 bottom
R82  10k  [RC0402N]  119.38 78.93 270 top
R83  2.2K  [RC0402N]  123.21 87.86 180 bottom
R84  100k  [RC0402N]  121.29 78.93 90 top
R85  2.2K  [RC0402N]  94.5 101.18 270 top
R86  1.24K  [RC0402N]  92.56 94.61 90 bottom
R87  1k  [RC0402N]  97.32 94.86 45 bottom
R88  1k  [RC0402N]  107.62 100.07 180 top
R89  10k  [RC0402N]  106.03 95.63 90 top
R90  10k  [RC0402N]  106.8 95.63 90 top
R91  10k  [RC0402N]  66.68 95.06 180 top
R92  45.3  [RC0402N]  97.3 96.44 225 bottom
R93  0  [RC0402N]  91.57 93.86 270 bottom
R94  10k  [RC0402N]  66.68 94.3 0 top
R95  0  [RC0402N]  97.99 101.18 270 top
R96  0  [RC0402N]  98.79 101.18 270 top
R97  0  [RC0402N]  96.43 101.18 270 top
R98  0  [RC0402N]  97.2 101.18 270 top
R99  45.3  [RC0402N]  99.65 99.48 270 top
R100  49.9  [RC0402N]  74.51 91.09 135 bottom
R101  0  [RC0402N]  66.54 93.65 90 bottom
R102  0  [RC0402N]  67.01 93.19 0 bottom
R103  10k  [RC0603N]  134.29 33.91 90 top
R105  22  [RC0402N]  71.17 86.73 0 top
R106  2.2K  [RC0402N]  69.96 97.6 180 top
R107  22  [RC0402N]  71.17 85.97 0 top
R108  2.2K  [RC0402N]  69.96 98.4 180 top
R109  2.2K  [RC0402N]  71.24 96.69 270 top
R110  10k  [RC0402N]  105.25 95.63 270 top
R111  0  [RC0402N]  63.38 81.09 90 bottom
R112  0  [RC0402N]  64.19 81.09 90 bottom
R114  0  [RC0402N]  86.55 98.92 90 bottom
R115  0  [RC0402N]  86.56 97.15 90 bottom
R116  0  [RC0402N]  62.05 91.16 180 bottom
R117  0  [RC0402N]  62.52 90.69 270 bottom
R118  0  [RC0402N]  88.78 83.5 90 bottom
R119  0  [RC0603N]  71.08 105.22 0 bottom
R120  1k  [RC0402N]  124.47 52.49 270 bottom
R121  10k  [RC0402N]  61.73 53.5 180 bottom
R122  10k  [RC0402N]  62.16 50.53 270 bottom
R123  10k  [RC0402N]  62.93 50.53 270 bottom
R124  1k  [RC0402N]  123.99 53.77 0 bottom
R125  1k  [RC0402N]  87.45 49.45 270 bottom
R126  1k  [RC0402N]  86.69 49.45 90 bottom
R127  0  [RC0402N]  53.94 61.36 180 top
R128  0  [RC0402N]  53.92 60.52 180 top
R129  51  [RC0402N]  110.01 99.46 90 top
R130  4.7K  [RC0402N]  62.47 61.19 270 top
R131  51  [RC0402N]  97.86 94.32 225 bottom
R132  4.7K  [RC0402N]  54.74 59.68 180 top
R133  10k  [RC0402N]  18.01 130.12 270 top
R134  10k  [RC0402N]  19.57 125.3 180 top
R135  100  [RC0402N]  19.57 126.08 180 top
R136  10k  [RC0402N]  46.15 125.65 180 top
R137  100k  [RC0402N]  47.1 126.95 0 top
R149  0  [RC0402N]  14.56 39.77 180 top
R152  0  [RC0402N]  52.98 119.05 0 bottom
R153  0  [RC0402N]  52.98 119.82 0 bottom
R154  10k  [RC0402N]  66.1 115.12 0 bottom
R155  10k  [RC0402N]  65.76 114.34 0 bottom
R159  4.99k  [RC0402N]  54.8 111.91 90 bottom
R160  0  [RC0402N]  7.31 63.68 180 top
R161  4.99k  [RC0402N]  55.57 111.91 90 bottom
R162  0  [RC0402N]  47.37 122.45 0 top
R163  0  [RC0402N]  13.16 14.11 180 top
R164  1M  [RC0402N]  29.02 36.98 0 bottom
R165  0  [RC0402N]  14.02 36.71 90 top
R166  0  [RC0402N]  58.59 111.16 270 bottom
R168  0  [RC0402N]  7.31 62.91 180 top
R169  4.7K  [RC0402N]  68.67 123.51 0 top
